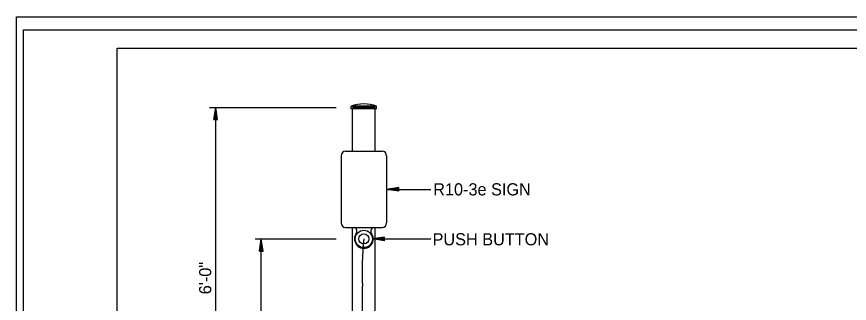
# Model space of a CAD drawing. Extents: x 1695551 to 1695718, y 544410 to 544516.
# Drawn here: x 1695551.3 to 1695602.6, y 544498.5 to 544516.2 of the extents above; entities that cross this region are included whole.
import ezdxf

# ---------------------------------------------------------------- set-up
doc = ezdxf.new("R2010")
doc.units = 0
for name, color, linetype in [('0_Plot Shape', 7, 'Continuous'), ('R_Border', 7, 'Continuous'), ('R_Draft', 7, 'Continuous'), ('R_No Plot', 7, 'Continuous')]:
    doc.layers.add(name, color=color, linetype=linetype)

msp = doc.modelspace()

# ---------------------------------------------------------------- linework, layer by layer
at = {"layer": '0_Plot Shape'}
msp.add_lwpolyline([(1695551.694, 544515.386), (1695716.694, 544515.386), (1695716.694, 544410.386), (1695551.694, 544410.386)], close=True, dxfattribs=at)
at = {"layer": 'R_Border'}
for p, q in [((1695557.469, 544514.251), (1695715.559, 544514.251)), ((1695557.469, 544411.521), (1695557.469, 544514.251))]:
    msp.add_line(p, q, dxfattribs=at)
at = {"layer": 'R_Draft'}
for p, q in [((1695563.171, 544510.601), (1695570.98, 544510.601)), ((1695563.433, 544509.851), (1695563.546, 544510.601)), ((1695563.452, 544509.851), (1695563.546, 544510.475)), ((1695563.471, 544509.851), (1695563.546, 544510.346)), ((1695563.49, 544509.851), (1695563.546, 544510.221)), ((1695563.546, 544487.501), (1695563.546, 544510.601)), ((1695563.658, 544509.851), (1695563.546, 544510.601)), ((1695563.639, 544509.851), (1695563.546, 544510.475)), ((1695563.62, 544509.851), (1695563.546, 544510.346)), ((1695563.601, 544509.851), (1695563.546, 544510.221)), ((1695573.464, 544510.676), (1695571.908, 544510.676)), ((1695571.908, 544510.526), (1695571.908, 544510.676)), ((1695573.464, 544510.526), (1695571.908, 544510.526)), ((1695573.389, 544510.601), (1695571.983, 544510.601)), ((1695571.983, 544507.901), (1695571.983, 544510.526)), ((1695573.389, 544507.901), (1695573.389, 544510.526)), ((1695573.464, 544510.526), (1695573.464, 544510.676)), ((1695563.433, 544509.851), (1695563.658, 544509.851)), ((1695563.509, 544509.851), (1695563.546, 544510.094)), ((1695563.528, 544509.851), (1695563.546, 544509.969)), ((1695563.582, 544509.851), (1695563.546, 544510.094)), ((1695563.563, 544509.851), (1695563.546, 544509.969)), ((1695571.28, 544507.628), (1695571.28, 544503.487)), ((1695571.553, 544507.901), (1695573.819, 544507.901)), ((1695574.092, 544507.628), (1695574.092, 544503.487)), ((1695574.842, 544505.67), (1695574.092, 544505.557)), ((1695574.842, 544505.651), (1695574.218, 544505.557)), ((1695574.842, 544505.632), (1695574.347, 544505.557)), ((1695574.842, 544505.613), (1695574.472, 544505.557)), ((1695574.842, 544505.594), (1695574.599, 544505.557)), ((1695574.842, 544505.575), (1695574.724, 544505.557)), ((1695574.842, 544505.445), (1695574.842, 544505.67)), ((1695574.092, 544505.557), (1695576.808, 544505.557)), ((1695574.842, 544505.445), (1695574.092, 544505.557)), ((1695574.842, 544505.464), (1695574.218, 544505.557)), ((1695574.842, 544505.483), (1695574.347, 544505.557)), ((1695574.842, 544505.502), (1695574.472, 544505.557)), ((1695574.842, 544505.521), (1695574.599, 544505.557)), ((1695574.842, 544505.54), (1695574.724, 544505.557)), ((1695571.553, 544503.214), (1695573.819, 544503.214)), ((1695571.983, 544488.101), (1695571.983, 544503.214)), ((1695573.389, 544488.101), (1695573.389, 544503.214)), ((1695565.983, 544502.501), (1695570.98, 544502.501)), ((1695566.246, 544501.751), (1695566.358, 544502.501)), ((1695566.358, 544487.501), (1695566.358, 544502.501)), ((1695566.471, 544501.751), (1695566.358, 544502.501)), ((1695573.967, 544502.614), (1695573.217, 544502.501)), ((1695573.217, 544502.501), (1695576.808, 544502.501)), ((1695573.967, 544502.389), (1695573.217, 544502.501)), ((1695573.967, 544502.595), (1695573.343, 544502.501)), ((1695573.967, 544502.407), (1695573.343, 544502.501)), ((1695573.967, 544502.576), (1695573.472, 544502.501)), ((1695573.967, 544502.427), (1695573.472, 544502.501)), ((1695573.967, 544502.557), (1695573.597, 544502.501)), ((1695573.967, 544502.445), (1695573.597, 544502.501)), ((1695573.967, 544502.538), (1695573.724, 544502.501)), ((1695573.967, 544502.465), (1695573.724, 544502.501)), ((1695573.967, 544502.519), (1695573.849, 544502.501)), ((1695573.967, 544502.484), (1695573.849, 544502.501)), ((1695573.967, 544502.389), (1695573.967, 544502.614)), ((1695566.264, 544501.751), (1695566.358, 544502.376)), ((1695566.283, 544501.751), (1695566.358, 544502.247)), ((1695566.302, 544501.751), (1695566.358, 544502.122)), ((1695566.322, 544501.751), (1695566.358, 544501.995)), ((1695566.452, 544501.751), (1695566.358, 544502.376)), ((1695566.433, 544501.751), (1695566.358, 544502.247)), ((1695566.414, 544501.751), (1695566.358, 544502.122)), ((1695566.395, 544501.751), (1695566.358, 544501.995)), ((1695566.246, 544501.751), (1695566.471, 544501.751)), ((1695566.34, 544501.751), (1695566.358, 544501.87)), ((1695566.376, 544501.751), (1695566.358, 544501.87)), ((1695572.592, 544483.092), (1695572.592, 544499.584))]:
    msp.add_line(p, q, dxfattribs=at)
for radius in [0.531, 0.312]:
    msp.add_circle((1695572.686, 544502.501), radius, dxfattribs=at)
for centre, radius, start, end in [((1695572.686, 544508.732), 2.093, 68.1777, 111.8223), ((1695571.553, 544507.628), 0.273, 90, 180), ((1695573.819, 544507.628), 0.273, 0, 90), ((1695571.553, 544503.487), 0.273, 180, 270), ((1695571.996, 544502.976), 0.263, 318.1972, 64.8044), ((1695573.376, 544502.976), 0.263, 115.1956, 221.8028), ((1695573.819, 544503.487), 0.273, 270, 0), ((1695572.686, 544502.501), 0.578, 148.7402, 31.2598), ((1695593.322, 544500.378), 20.744, 174.1251, 182.1939)]:
    msp.add_arc(centre, radius, start, end, dxfattribs=at)
at = {"layer": 'R_No Plot'}
msp.add_line((1695551.268, 544516.198), (1695717.935, 544516.198), dxfattribs=at)
msp.add_lwpolyline([(1695551.265, 544516.198), (1695717.935, 544516.198), (1695717.935, 544409.529), (1695551.265, 544409.529)], close=True, dxfattribs=at)

# ---------------------------------------------------------------- texts
at = {"layer": 'R_Draft'}
for s, p in [('R10-3e SIGN', (1695576.966, 544505.182)), ('PUSH BUTTON', (1695576.924, 544502.105))]:
    msp.add_text(s, height=0.75, dxfattribs=at).set_placement(p)
msp.add_text('6\'-0"', height=0.75, rotation=90, dxfattribs=at).set_placement((1695563.272, 544499.089))

doc.saveas('drawing.dxf')
